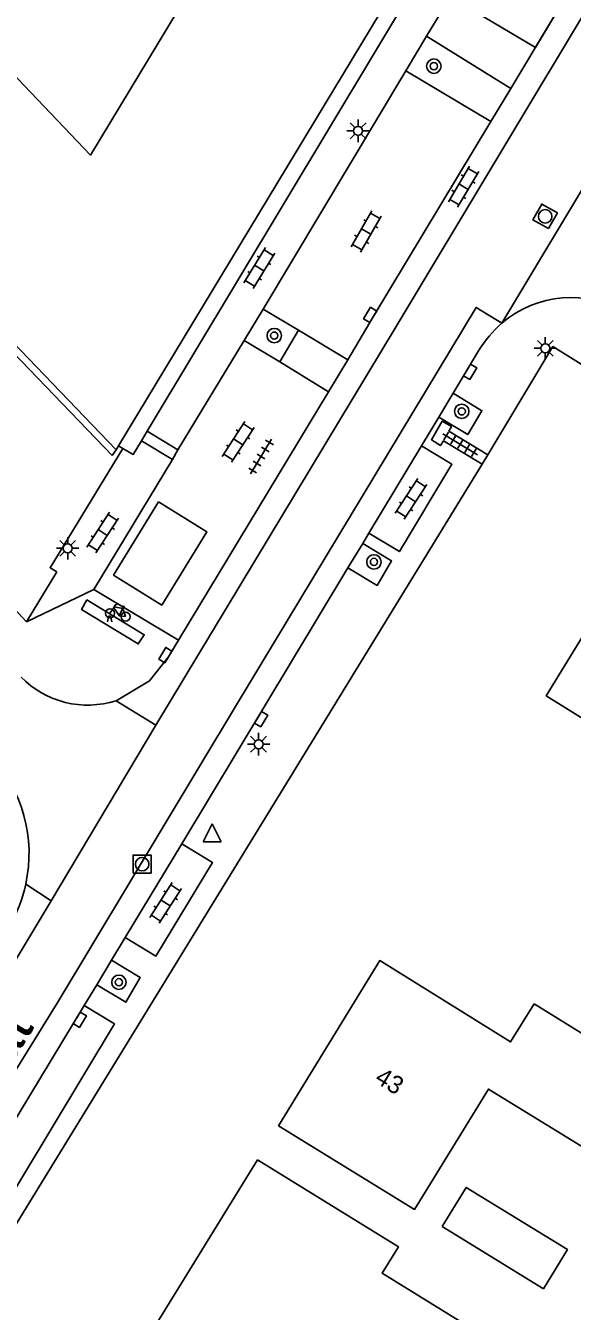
# Model space of a CAD drawing. Extents: x 136000 to 141014, y 402000 to 403500.
# Drawn here: x 137763.6 to 137794, y 402262.7 to 402334.1 of the extents above; entities that cross this region are included whole.
import ezdxf

# ---------------------------------------------------------------- set-up
doc = ezdxf.new("R2010")
doc.units = 0
for name, color, linetype in [('bp-grn-parkeervak', 7, 'Continuous'), ('gg-afsc-erfafscheiding', 7, 'Continuous'), ('gg-anno-huisnummerreeks BGT', 7, 'Continuous'), ('gg-anno-openbare ruimte label', 7, 'Continuous'), ('gg-bbg-abri', 7, 'Continuous'), ('gg-bbg-gedigitaliseerde bebouwing', 7, 'Continuous'), ('gg-bbg-gedigitaliseerde bijgebouw', 7, 'Continuous'), ('gg-bbg-hoofdgebouw', 7, 'Continuous'), ('gg-knt-verharding', 7, 'Continuous'), ('gg-knt-verharding nz', 7, 'Continuous'), ('gt-grn-groengrens', 7, 'Continuous'), ('gt-grn-weggrens', 7, 'Continuous'), ('gt-symb-boom', 7, 'Continuous'), ('gt-symb-fietsenrek', 7, 'Continuous'), ('gt-symb-klinker verharding', 7, 'Continuous'), ('gt-symb-kolk', 7, 'Continuous'), ('gt-symb-lichtmast', 7, 'Continuous'), ('gt-symb-rioolschacht', 7, 'Continuous'), ('gt-symb-tegel verharding', 7, 'Continuous'), ('gt-symb-waterafsluiter', 7, 'Continuous')]:
    doc.layers.add(name, color=color, linetype=linetype)

# ---------------------------------------------------------------- blocks, each defined once
blk = doc.blocks.new('gt0-RS')
at = {"layer": 'gt-symb-rioolschacht'}
blk.add_lwpolyline([(-0.5, -0.5), (0.5, -0.5), (0.5, 0.5), (-0.5, 0.5)], close=True, dxfattribs=at)
blk.add_circle((0, 0), 0.375, dxfattribs=at)
blk = doc.blocks.new('gt0-KL1')
at = {"layer": 'gt-symb-klinker verharding'}
for p, q in [((-1.15, 0.3), (1.15, 0.3)), ((-1, -0.3), (-1, 0.3)), ((-0.5, 0.3), (-0.5, 0.45)), ((0, -0.3), (0, 0.3)), ((0.5, 0.3), (0.5, 0.45)), ((1, -0.3), (1, 0.3)), ((-1.15, -0.3), (1.15, -0.3)), ((-0.5, -0.45), (-0.5, -0.3)), ((0.5, -0.45), (0.5, -0.3))]:
    blk.add_line(p, q, dxfattribs=at)
blk = doc.blocks.new('gt0-TEG1')
at = {"layer": 'gt-symb-tegel verharding'}
for p, q in [((-1.125, 0), (1.125, 0)), ((-0.9, -0.25), (-0.9, 0.25)), ((-0.45, -0.25), (-0.45, 0.25)), ((0, -0.25), (0, 0.25)), ((0.45, -0.25), (0.45, 0.25)), ((0.9, -0.25), (0.9, 0.25))]:
    blk.add_line(p, q, dxfattribs=at)
blk = doc.blocks.new('gt0-BOOM')
at = {"layer": 'gt-symb-boom'}
for radius in [0.4, 0.2]:
    blk.add_circle((0, 0), radius, dxfattribs=at)
blk = doc.blocks.new('gt0-KOLK')
at = {"layer": 'gt-symb-kolk'}
blk.add_lwpolyline([(0, 0), (0.375, 0), (0.375, 0.4), (-0.375, 0.4), (-0.375, 0), (0, 0)], dxfattribs=at)
blk = doc.blocks.new('gt0-LMAST')
at = {"layer": 'gt-symb-lichtmast'}
for p, q in [((-0.182, 0.173), (-0.447, 0.438)), ((-0.005, 0.246), (-0.005, 0.621)), ((0.172, 0.173), (0.437, 0.438)), ((-0.255, -0.004), (-0.63, -0.004)), ((-0.182, -0.181), (-0.447, -0.446)), ((-0.005, -0.254), (-0.005, -0.629)), ((0.437, -0.446), (0.172, -0.181)), ((0.245, -0.004), (0.62, -0.004))]:
    blk.add_line(p, q, dxfattribs=at)
blk.add_circle((-0.005, -0.004), 0.25, dxfattribs=at)
blk = doc.blocks.new('gt0-WAFSL')
at = {"layer": 'gt-symb-waterafsluiter'}
for p, q in [((-0.5, -0.333), (0, 0.667)), ((0, 0.667), (0.5, -0.333)), ((0.5, -0.333), (-0.5, -0.333))]:
    blk.add_line(p, q, dxfattribs=at)
blk = doc.blocks.new('gt0-FREK')
at = {"layer": 'gt-symb-fietsenrek'}
for p, q in [((0.259, 0.762), (0.294, 0.823)), ((0.54, 0.335), (0.259, 0.762)), ((0.294, 0.823), (0.767, 0.714)), ((0.767, 0.714), (0.54, 0.335)), ((0.757, 0.841), (0.866, 0.816)), ((0.767, 0.714), (0.84, 0.822)), ((0.895, 0.252), (0.767, 0.714))]:
    blk.add_line(p, q, dxfattribs=at)
for points in [[(0.036, 0.476), (0.228, 0.708), (0.259, 0.762)], [(0.294, 0.823), (0.36, 0.937), (0.452, 0.935)], [(-0.124, 0), (-0.047, 0.312), (0.053, 0.312), (0.12, 0)], [(0.54, 0.335), (0.555, 0.305), (0.895, 0.252)]]:
    blk.add_lwpolyline(points, dxfattribs=at)
for centre in [(0.036, 0.476), (0.895, 0.252)]:
    blk.add_circle(centre, 0.252, dxfattribs=at)

msp = doc.modelspace()

# ---------------------------------------------------------------- linework, layer by layer
at = {"layer": 'bp-grn-parkeervak'}
msp.add_lwpolyline([(137793.194, 402334.986), (137791.917, 402332.853), (137787.21, 402335.672), (137788.491, 402337.789)], dxfattribs=at)
at = {"layer": 'gg-afsc-erfafscheiding'}
for p, q in [((137772.078, 402310.522), (137771.773, 402309.987)), ((137763.671, 402300.99), (137767.403, 402302.78))]:
    msp.add_line(p, q, dxfattribs=at)
at = {"layer": 'gg-bbg-abri'}
msp.add_lwpolyline([(137771.004, 402307.648), (137773.673, 402305.981), (137771.175, 402301.907), (137768.507, 402303.574), (137771.004, 402307.648)], dxfattribs=at)
at = {"layer": 'gg-bbg-gedigitaliseerde bebouwing'}
for points in [[(137748.472, 402346.554), (137759.424, 402357.036), (137778.556, 402345.635), (137767.214, 402326.882), (137748.472, 402346.554)], [(137777.65, 402273.02), (137785.211, 402268.38), (137789.314, 402275.056), (137796.893, 402270.397), (137799.679, 402274.93), (137791.86, 402279.78)], [(137766.14, 402254.34), (137774.07, 402249.444), (137781.197, 402260.995), (137786.42, 402257.772), (137788.745, 402261.54), (137783.407, 402264.833), (137784.312, 402266.301), (137776.5, 402271.13)]]:
    msp.add_lwpolyline(points, dxfattribs=at)
at = {"layer": 'gg-bbg-gedigitaliseerde bijgebouw'}
msp.add_lwpolyline([(137786.739, 402267.422), (137788.072, 402269.594), (137793.694, 402266.145), (137792.361, 402263.972), (137786.739, 402267.422)], dxfattribs=at)
at = {"layer": 'gg-bbg-hoofdgebouw'}
for p, q in [((137736.625, 402343.863), (137768.641, 402310.531)), ((137768.771, 402310.747), (137784.789, 402337.23)), ((137768.641, 402310.531), (137768.771, 402310.747)), ((137776.5, 402271.13), (137766.14, 402254.34))]:
    msp.add_line(p, q, dxfattribs=at)
for points in [[(137795.216, 402301.282), (137792.52, 402296.88), (137799.26, 402292.69), (137798.37, 402291.21), (137801.39, 402289.34)], [(137777.65, 402273.02), (137783.28, 402282.18), (137790.54, 402277.67), (137791.86, 402279.78)]]:
    msp.add_lwpolyline(points, dxfattribs=at)
at = {"layer": 'gg-knt-verharding'}
for p, q in [((137784.719, 402331.566), (137785.879, 402333.474)), ((137790.558, 402330.584), (137785.879, 402333.474)), ((137789.443, 402328.737), (137784.719, 402331.566)), ((137790.558, 402330.584), (137789.443, 402328.737)), ((137775.744, 402316.588), (137776.804, 402318.338)), ((137778.77, 402317.168), (137776.804, 402318.338)), ((137778.77, 402317.168), (137777.733, 402315.404)), ((137781.511, 402315.511), (137778.77, 402317.168)), ((137775.744, 402316.588), (137777.733, 402315.404)), ((137781.511, 402315.511), (137780.439, 402313.738)), ((137787.348, 402313.664), (137788.76, 402316.014)), ((137780.439, 402313.738), (137772.109, 402299.972)), ((137787.348, 402313.664), (137786.55, 402312.339)), ((137786.55, 402312.339), (137785.59, 402310.745)), ((137770.049, 402311.033), (137770.367, 402311.562)), ((137772.078, 402310.522), (137770.367, 402311.562)), ((137768.641, 402310.531), (137768.433, 402310.202)), ((137770.049, 402311.033), (137771.773, 402309.987)), ((137785.59, 402310.745), (137782.677, 402305.905)), ((137788.96, 402309.729), (137789.277, 402310.254)), ((137782.677, 402305.905), (137782.331, 402305.33)), ((137782.331, 402305.33), (137781.516, 402303.976)), ((137763.671, 402300.99), (137765.349, 402303.755)), ((137781.516, 402303.976), (137772.286, 402288.661)), ((137761.604, 402303.183), (137763.671, 402300.99)), ((137772.286, 402288.661), (137769.15, 402283.462)), ((137769.15, 402283.462), (137768.388, 402282.199)), ((137768.388, 402282.199), (137767.57, 402280.844)), ((137767.57, 402280.844), (137766.873, 402279.688)), ((137766.873, 402279.688), (137758.212, 402265.375))]:
    msp.add_line(p, q, dxfattribs=at)
for points in [[(137768.433, 402310.202), (137736.217, 402343.711), (137736.302, 402348.796), (137739.353, 402351.721)], [(137797.249, 402341.692), (137795.038, 402338.065), (137790.558, 402330.584)], [(137770.367, 402311.562), (137785.525, 402336.785), (137784.789, 402337.23)], [(137789.443, 402328.737), (137782.92, 402317.907), (137781.511, 402315.511)], [(137789.277, 402310.254), (137792.896, 402316.257), (137796.264, 402314.159)], [(137786.55, 402312.339), (137788.161, 402311.369), (137788.952, 402312.698), (137787.348, 402313.664)], [(137788.96, 402309.729), (137786.811, 402311.016), (137786.651, 402310.766), (137786.143, 402311.083), (137786.748, 402312.113), (137787.259, 402311.818), (137787.117, 402311.553), (137789.277, 402310.254)], [(137769.016, 402310.606), (137764.98, 402303.981), (137765.349, 402303.755)], [(137770.049, 402311.033), (137769.593, 402310.274), (137769.016, 402310.606)], [(137719.672, 402195.595), (137722.912, 402200.968), (137728.869, 402210.947), (137739.968, 402229.279), (137753.744, 402252.136), (137762.084, 402265.932), (137788.96, 402309.729)], [(137781.516, 402303.976), (137783.129, 402303.005), (137783.938, 402304.363), (137782.331, 402305.33)], [(137772.109, 402299.972), (137771.548, 402299.032), (137770.504, 402297.703), (137768.643, 402296.606)], [(137767.57, 402280.844), (137769.181, 402279.872), (137769.981, 402281.238), (137768.388, 402282.199)]]:
    msp.add_lwpolyline(points, dxfattribs=at)
for centre, radius, start, end in [((137793.905, 402313.054), 5.923, 58.78092, 130.55314), ((137794.521, 402312.486), 6.756, 131.39929, 148.52275), ((137767.065, 402301.543), 5.183, 224.45346, 287.72962), ((137755.858, 402288.129), 7.954, 347.58656, 43.02147), ((137755.89, 402288.113), 7.919, 329.26425, 347.64604)]:
    msp.add_arc(centre, radius, start, end, dxfattribs=at)
at = {"layer": 'gg-knt-verharding nz'}
for p, q in [((137785.879, 402333.474), (137792.978, 402345.201)), ((137776.804, 402318.338), (137784.719, 402331.566)), ((137772.078, 402310.522), (137775.744, 402316.588)), ((137780.439, 402313.738), (137777.733, 402315.404)), ((137771.773, 402309.987), (137767.403, 402302.78)), ((137767.403, 402302.78), (137772.109, 402299.972)), ((137768.643, 402296.606), (137770.851, 402295.247)), ((137763.626, 402286.419), (137765.046, 402285.493))]:
    msp.add_line(p, q, dxfattribs=at)
for points in [[(137770.851, 402295.247), (137784.133, 402317.27), (137806.759, 402354.967), (137830.013, 402393.465)], [(137790.054, 402317.554), (137788.634, 402318.429), (137775.335, 402296.375), (137765.378, 402279.824)], [(137785.59, 402310.745), (137787.286, 402309.724), (137784.374, 402304.883), (137782.677, 402305.905)], [(137767.028, 402302.203), (137766.719, 402301.672), (137769.876, 402299.759), (137770.206, 402300.265), (137767.028, 402302.203)], [(137772.286, 402288.661), (137773.986, 402287.635), (137770.857, 402282.432), (137769.15, 402283.462)], [(137765.046, 402285.493), (137754.115, 402267.355), (137745.603, 402253.195), (137727.992, 402224.133), (137716.278, 402204.698), (137706.9, 402189.211), (137704.755, 402185.699)], [(137765.378, 402279.824), (137756.639, 402265.721), (137748.332, 402251.619), (137736.06, 402231.612), (137718.915, 402203.173), (137709.365, 402187.413), (137707.351, 402184.114)], [(137766.873, 402279.688), (137768.561, 402278.67), (137759.919, 402264.342), (137758.212, 402265.375)]]:
    msp.add_lwpolyline(points, dxfattribs=at)
at = {"layer": 'gt-grn-groengrens'}
msp.add_line((137769.016, 402310.606), (137768.771, 402310.747), dxfattribs=at)
at = {"layer": 'gt-grn-weggrens'}
for p, q in [((137790.054, 402317.554), (137796.711, 402328.65)), ((137765.046, 402285.493), (137770.851, 402295.247))]:
    msp.add_line(p, q, dxfattribs=at)

# ---------------------------------------------------------------- block references
at = {"layer": 'gt-symb-boom'}
for p in [(137786.283, 402331.817), (137777.423, 402316.864), (137787.83, 402312.661), (137782.957, 402304.306), (137768.799, 402280.982)]:
    msp.add_blockref('gt0-BOOM', p, dxfattribs=at)
at = {"layer": 'gt-symb-fietsenrek', "rotation": 2.4376774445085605}
msp.add_blockref('gt0-FREK', (137768.285, 402300.981), dxfattribs=at)
at = {"layer": 'gt-symb-klinker verharding'}
for p, rotation in [((137787.932, 402325.127), 59.28180933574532), ((137782.526, 402322.639), 59.871399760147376), ((137776.592, 402320.618), 58.66279427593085), ((137775.419, 402310.963), -123.16559931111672), ((137785.02, 402307.801), -123.16559931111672), ((137767.903, 402305.933), 56.91369260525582), ((137771.396, 402285.382), 57.32672252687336)]:
    msp.add_blockref('gt0-KL1', p, dxfattribs=dict(at, rotation=rotation))
at = {"layer": 'gt-symb-kolk'}
for p, rotation in [((137782.92, 402317.907), 58.93383577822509), ((137788.128, 402314.96), -120.94299869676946), ((137771.548, 402299.032), 59.1940216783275), ((137776.524, 402295.684), -121.04817574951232), ((137766.46, 402279.004), -121.10630715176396)]:
    msp.add_blockref('gt0-KOLK', p, dxfattribs=dict(at, rotation=rotation))
at = {"layer": 'gt-symb-lichtmast'}
for p in [(137782.083, 402328.231), (137792.475, 402316.162), (137765.962, 402305.065), (137776.56, 402294.193)]:
    msp.add_blockref('gt0-LMAST', p, dxfattribs=at)
at = {"layer": 'gt-symb-rioolschacht', "rotation": 60.752581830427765}
msp.add_blockref('gt0-RS', (137792.461, 402323.479), dxfattribs=at)
at = {"layer": 'gt-symb-rioolschacht'}
msp.add_blockref('gt0-RS', (137770.09, 402287.535), dxfattribs=at)
at = {"layer": 'gt-symb-tegel verharding'}
for p, rotation in [((137776.693, 402310.156), -121.13079914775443), ((137787.738, 402310.832), -31.20949091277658)]:
    msp.add_blockref('gt0-TEG1', p, dxfattribs=dict(at, rotation=rotation))
at = {"layer": 'gt-symb-waterafsluiter'}
msp.add_blockref('gt0-WAFSL', (137773.971, 402289.109), dxfattribs=at)

# ---------------------------------------------------------------- texts
at = {"layer": 'gg-anno-huisnummerreeks BGT'}
msp.add_text('43', height=1, rotation=328.4, dxfattribs=at).set_placement((137782.939, 402275.471))
at = {"layer": 'gg-anno-openbare ruimte label'}
msp.add_text('Slimstraat', height=2.5, rotation=58.9, dxfattribs=at).set_placement((137756.442, 402265.782))

doc.saveas('drawing.dxf')
